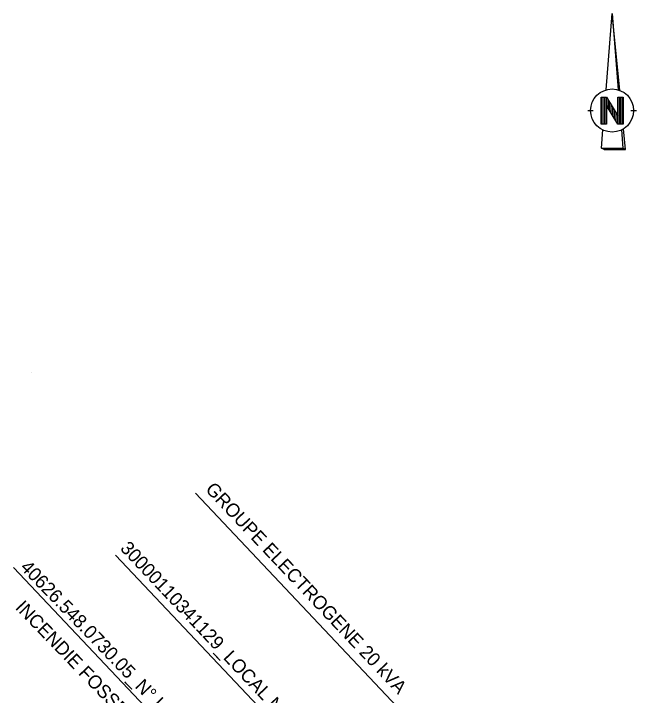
# Model space of a CAD drawing. Extents: x 704421 to 705059, y 7058908 to 7059523.
# Drawn here: x 704733.9 to 704849.6, y 7059396.7 to 7059523.3 of the extents above; entities that cross this region are included whole.
import ezdxf

# ---------------------------------------------------------------- set-up
doc = ezdxf.new("R2010")
doc.units = 0
for name, color, linetype in [('DH_NORD', 7, 'Continuous'), ('LIB_08', 7, 'Continuous'), ('RES_EAU BASSE PRESSION', 7, 'Continuous')]:
    doc.layers.add(name, color=color, linetype=linetype)

msp = doc.modelspace()

# ---------------------------------------------------------------- linework, layer by layer
at = {"layer": 'DH_NORD'}
for p, q in [((704843.93, 7059509.14), (704845.06, 7059523.31)), ((704845.06, 7059523.31), (704846.19, 7059509.14)), ((704846.47, 7059509.05), (704845.06, 7059523.31)), ((704843, 7059507.81), (704844.01, 7059507.81)), ((704843, 7059502.8), (704843, 7059507.81)), ((704843.1, 7059502.8), (704843.1, 7059507.81)), ((704843.4, 7059502.8), (704843.4, 7059507.81)), ((704843.7, 7059502.8), (704843.7, 7059507.81)), ((704844, 7059502.8), (704844, 7059507.81)), ((704844.01, 7059507.81), (704846.13, 7059504.34)), ((704844.3, 7059505.79), (704844.3, 7059507.34)), ((704846.13, 7059504.34), (704846.13, 7059507.81)), ((704846.13, 7059507.81), (704847.13, 7059507.81)), ((704846.4, 7059502.8), (704846.4, 7059507.81)), ((704846.7, 7059502.8), (704846.7, 7059507.81)), ((704847, 7059502.8), (704847, 7059507.81)), ((704847.13, 7059507.81), (704847.13, 7059502.8)), ((704846.12, 7059502.8), (704844, 7059506.27)), ((704844, 7059506.27), (704844, 7059502.8)), ((704844.6, 7059505.3), (704844.6, 7059506.85)), ((704844.9, 7059504.8), (704844.9, 7059506.36)), ((704845.2, 7059504.31), (704845.2, 7059505.86)), ((704840.56, 7059505.31), (704841.56, 7059505.31)), ((704845.5, 7059503.82), (704845.5, 7059505.37)), ((704845.8, 7059503.33), (704845.8, 7059504.88)), ((704846.1, 7059502.83), (704846.1, 7059504.39)), ((704848.56, 7059505.31), (704849.56, 7059505.31)), ((704844, 7059502.8), (704843, 7059502.8)), ((704847.13, 7059502.8), (704846.12, 7059502.8)), ((704847.56, 7059498.06), (704847.18, 7059501.91)), ((704843.06, 7059498.31), (704843.33, 7059501.7)), ((704846.79, 7059501.7), (704847.06, 7059498.31)), ((704843.06, 7059498.31), (704847.06, 7059498.31)), ((704843.56, 7059498.06), (704843.06, 7059498.31)), ((704843.56, 7059498.06), (704847.56, 7059498.06)), ((704847.56, 7059498.06), (704847.06, 7059498.31))]:
    msp.add_line(p, q, dxfattribs=at)
msp.add_circle((704845.06, 7059505.31), 4, dxfattribs=at)
at = {"layer": 'LIB_08'}
for points in [[(704767.68, 7059434.23), (704806.21, 7059393.39), (704797.62, 7059353.45)], [(704752.82, 7059422.73), (704790.94, 7059382.33), (704789.35, 7059365.71)], [(704733.91, 7059420.43), (704775.36, 7059376.5), (704782.12, 7059355.95)]]:
    msp.add_lwpolyline(points, dxfattribs=at)
at = {"layer": 'RES_EAU BASSE PRESSION'}
msp.add_line((704737.29, 7059456.62), (704737.29, 7059456.62), dxfattribs=at)

# ---------------------------------------------------------------- texts
at = {"layer": 'LIB_08'}
for s, rotation, p in [('GROUPE ELECTROGENE 20 kVA', 313.3307, (704769.38, 7059434.8)), ('30000110341129_LOCAL N° 00001', 313.3307, (704753.56, 7059423.84)), ('40626.548.0730.05_N° LOCAL 00000', 313.9654, (704735, 7059420.29)), ('INCENDIE FOSSE ENTERREE', 313.9654, (704734.08, 7059412.84))]:
    msp.add_text(s, height=2.5, rotation=rotation, dxfattribs=at).set_placement(p)

doc.saveas('drawing.dxf')
